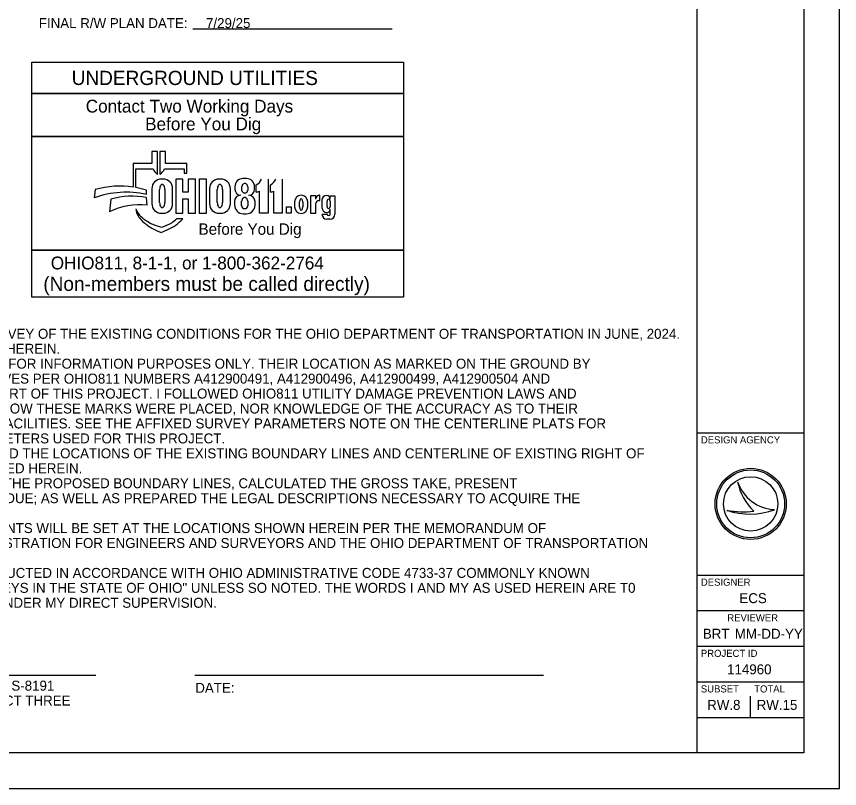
# Model space of a CAD drawing. Extents: x 0 to 34, y 0 to 22.
# Drawn here: x 22.43 to 34, y 0 to 10.85 of the extents above; entities that cross this region are included whole.
import ezdxf

# ---------------------------------------------------------------- set-up
doc = ezdxf.new("R2010")
doc.units = 0
for name, color, linetype in [('Default', 7, 'Continuous'), ('SH_Border', 7, 'Continuous'), ('SH_Cut_Line', 7, 'Continuous'), ('SH_Data', 7, 'Continuous'), ('SH_Text', 7, 'Continuous')]:
    doc.layers.add(name, color=color, linetype=linetype)

msp = doc.modelspace()

# ---------------------------------------------------------------- linework, layer by layer
at = {"layer": 'Default'}
for p, q in [((17.674, 1.594), (23.542, 1.594)), ((24.937, 1.594), (29.837, 1.594))]:
    msp.add_line(p, q, dxfattribs=at)
at = {"layer": 'SH_Border'}
for p, q in [((32, 0.5), (32, 21.5)), ((32, 5), (33.5, 5)), ((32, 3), (33.5, 3)), ((32, 2.5), (33.5, 2.5)), ((32, 2), (33.5, 2)), ((32, 1.5), (33.5, 1.5)), ((32, 1), (33.5, 1))]:
    msp.add_line(p, q, dxfattribs=at)
msp.add_lwpolyline([(1.5, 21.5), (33.5, 21.5), (33.5, 0.5), (1.5, 0.5)], close=True, dxfattribs=at)
at = {"layer": 'SH_Cut_Line'}
msp.add_lwpolyline([(0, 0), (34, 0), (34, 22), (0, 22)], close=True, dxfattribs=at)
at = {"layer": 'SH_Data'}
for p, q in [((24.412, 8.952), (24.332, 8.952)), ((24.332, 8.952), (24.332, 8.785)), ((24.412, 8.635), (24.412, 8.952)), ((24.524, 8.952), (24.444, 8.952)), ((24.444, 8.952), (24.444, 8.635)), ((24.524, 8.785), (24.524, 8.952)), ((24.332, 8.785), (24.069, 8.785)), ((24.069, 8.785), (24.069, 8.451)), ((24.107, 8.444), (24.107, 8.708)), ((24.107, 8.708), (24.348, 8.708)), ((24.508, 8.708), (24.786, 8.708)), ((24.821, 8.785), (24.524, 8.785)), ((24.786, 8.708), (24.786, 8.645)), ((24.821, 8.645), (24.821, 8.785)), ((24.786, 8.645), (24.821, 8.645)), ((25.661, 8.571), (25.612, 8.571)), ((24.489, 8.564), (24.464, 8.564)), ((24.767, 8.563), (24.666, 8.563)), ((24.666, 8.563), (24.666, 8.085)), ((25.3, 8.564), (25.275, 8.564)), ((25.498, 8.457), (25.498, 8.42)), ((25.597, 8.403), (25.597, 8.462)), ((25.678, 8.462), (25.678, 8.403)), ((25.775, 8.42), (25.775, 8.457)), ((25.798, 8.382), (25.798, 8.484)), ((25.965, 8.563), (25.965, 8.085)), ((25.998, 8.382), (25.998, 8.484)), ((26.165, 8.563), (26.165, 8.085)), ((23.534, 8.417), (23.52, 8.3)), ((24.253, 8.349), (24.253, 8.407)), ((24.331, 8.43), (24.331, 8.218)), ((24.44, 8.235), (24.44, 8.418)), ((24.514, 8.418), (24.514, 8.235)), ((24.623, 8.218), (24.623, 8.43)), ((25.142, 8.43), (25.142, 8.218)), ((25.25, 8.235), (25.25, 8.418)), ((25.325, 8.418), (25.325, 8.235)), ((25.434, 8.218), (25.434, 8.43)), ((25.846, 8.085), (25.846, 8.396)), ((26.046, 8.085), (26.046, 8.396)), ((26.694, 8.336), (26.688, 8.336)), ((26.694, 8.261), (26.694, 8.336)), ((23.755, 8.281), (23.733, 8.102)), ((24.263, 8.198), (24.254, 8.304)), ((24.767, 8.085), (24.767, 8.287)), ((25.493, 8.25), (25.493, 8.199)), ((25.593, 8.19), (25.593, 8.252)), ((25.678, 8.252), (25.678, 8.19)), ((25.781, 8.199), (25.781, 8.25)), ((26.339, 8.176), (26.339, 8.243)), ((26.406, 8.174), (26.406, 8.243)), ((26.454, 8.243), (26.454, 8.174)), ((26.521, 8.243), (26.521, 8.176)), ((26.634, 8.328), (26.561, 8.328)), ((26.561, 8.328), (26.561, 8.085)), ((26.634, 8.281), (26.634, 8.328)), ((26.683, 8.261), (26.694, 8.261)), ((26.723, 8.163), (26.723, 8.267)), ((26.795, 8.177), (26.795, 8.253)), ((26.837, 8.283), (26.837, 8.329)), ((26.837, 8.329), (26.903, 8.329)), ((26.837, 8.253), (26.837, 8.177)), ((26.903, 8.329), (26.903, 8.071)), ((24.106, 8.145), (24.111, 8.118)), ((26.634, 8.085), (26.634, 8.212)), ((26.837, 8.071), (26.837, 8.14)), ((24.464, 8.085), (24.489, 8.085)), ((24.666, 8.085), (24.767, 8.085)), ((24.765, 8.005), (24.679, 8.005)), ((24.762, 8.002), (24.765, 8.005)), ((25.275, 8.085), (25.3, 8.085)), ((25.614, 8.078), (25.66, 8.078)), ((25.965, 8.085), (25.846, 8.085)), ((26.165, 8.085), (26.046, 8.085)), ((26.561, 8.085), (26.634, 8.085)), ((26.723, 8.071), (26.795, 8.071)), ((26.833, 8.001), (26.792, 8.001)), ((24.471, 7.884), (24.382, 7.914)), ((24.532, 7.91), (24.471, 7.884)), ((24.406, 7.838), (24.462, 7.814)), ((24.462, 7.814), (24.557, 7.855)), ((27.868, 6.906), (22.643, 6.906)), ((32.567, 4.31), (32.567, 4.31)), ((32.75, 4), (32.75, 4)), ((32.417, 3.91), (32.417, 3.91)), ((33.087, 3.919), (33.087, 3.919)), ((32.75, 1), (32.75, 1.3))]:
    msp.add_line(p, q, dxfattribs=at)
for points in [[(22.643, 10.206), (27.868, 10.206), (27.868, 9.766), (22.643, 9.766)], [(22.643, 9.766), (27.868, 9.766), (27.868, 9.161), (22.643, 9.161)], [(22.643, 9.161), (27.868, 9.161), (27.868, 7.566), (22.643, 7.566)], [(26.223, 8.174), (26.289, 8.174), (26.289, 8.085), (26.223, 8.085)], [(22.643, 7.566), (27.868, 7.566), (27.868, 6.906), (22.643, 6.906)]]:
    msp.add_lwpolyline(points, close=True, dxfattribs=at)
for points in [[(24.767, 8.287), (24.843, 8.287), (24.843, 8.085), (24.945, 8.085), (24.945, 8.563), (24.843, 8.563), (24.843, 8.382), (24.767, 8.382), (24.767, 8.563)], [(24.995, 8.085), (25.098, 8.085), (25.098, 8.563), (24.995, 8.563), (24.995, 8.085)], [(25.579, 8.337), (25.579, 8.337)], [(25.695, 8.337), (25.695, 8.337)]]:
    msp.add_lwpolyline(points, dxfattribs=at)
for radius in [0.5, 0.477, 0.477, 0.382]:
    msp.add_circle((32.75, 4), radius, dxfattribs=at)
for centre, radius, start, end in [((24.484, 8.763), 0.147, 201.9296, 240.7469), ((24.372, 8.763), 0.147, 299.2531, 338.0704), ((25.612, 8.457), 0.114, 90, 180), ((25.661, 8.457), 0.114, 0, 90), ((23.878, 7.242), 1.224, 81.0007, 106.3144), ((24.464, 8.43), 0.134, 90, 180), ((24.489, 8.43), 0.134, 0, 90), ((25.275, 8.43), 0.134, 90, 180), ((25.3, 8.43), 0.134, 0, 90), ((25.747, 8.606), 0.132, 292.5572, 340.7355), ((25.947, 8.606), 0.132, 292.5572, 340.7355), ((23.972, 7.047), 1.332, 77.8238, 109.8274), ((23.878, 7.242), 1.224, 72.1402, 79.2074), ((25.579, 8.25), 0.0865, 90, 180), ((25.582, 8.42), 0.0837, 180, 268.1442), ((25.691, 8.42), 0.0837, 272.2058, 0), ((25.695, 8.25), 0.0865, 0, 90), ((25.786, 8.514), 0.132, 275.1733, 297.0931), ((25.986, 8.514), 0.132, 275.1733, 297.0931), ((26.434, 8.243), 0.0956, 92.5886, 180), ((26.426, 8.243), 0.0956, 0, 87.4114), ((26.688, 8.281), 0.0548, 90, 180), ((26.791, 8.267), 0.0686, 92.6865, 180), ((26.785, 8.283), 0.0524, 0, 86.9262), ((24.054, 7.229), 1.094, 79.44, 105.8467), ((24.464, 8.218), 0.134, 180, 270), ((24.489, 8.218), 0.134, 270, 0), ((25.275, 8.218), 0.134, 180, 270), ((25.3, 8.218), 0.134, 270, 0), ((26.683, 8.212), 0.0493, 90, 180), ((24.161, 7.254), 0.95, 83.8248, 116.8021), ((24.386, 8.252), 0.3, 201.0457, 232.5314), ((24.322, 8.154), 0.214, 189.6817, 216.0884), ((25.614, 8.199), 0.121, 180, 270), ((25.66, 8.199), 0.121, 270, 0), ((26.434, 8.176), 0.0956, 180, 267.4114), ((26.426, 8.176), 0.0956, 272.5886, 0), ((26.792, 8.163), 0.0692, 180, 265.7132), ((26.791, 8.14), 0.0467, 264.7825, 0), ((24.522, 8.3), 0.461, 216.0884, 235.7167), ((24.674, 8.628), 0.773, 232.5314, 241.794), ((24.318, 8.404), 0.538, 293.4582, 312.0712), ((24.318, 8.404), 0.599, 293.4582, 317.8286), ((26.792, 8.071), 0.0699, 180, 270), ((26.833, 8.071), 0.0699, 270, 0), ((24.77, 8.664), 0.903, 235.7167, 246.2325), ((24.547, 8.391), 0.504, 241.794, 250.9821), ((33.116, 4.498), 0.58, 198.9257, 198.9319), ((33.347, 4.47), 0.796, 191.6379, 191.6421), ((33.116, 4.498), 0.58, 198.9319, 267.1657), ((33.347, 4.47), 0.796, 191.6421, 226.0947), ((32.739, 4.87), 1.013, 251.4576, 290.0832), ((32.648, 5.154), 1.266, 259.4964, 259.4995), ((32.739, 4.87), 1.013, 251.4527, 251.4576), ((32.648, 5.154), 1.266, 259.4995, 276.6672)]:
    msp.add_arc(centre, radius, start, end, dxfattribs=at)
for centre, major_axis, ratio, start_param, end_param in [((24.477, 8.418), (0, 0.0723), 0.514403, 4.712389, 7.853982), ((25.288, 8.418), (0, 0.0723), 0.514403, 4.712389, 7.853982), ((25.637, 8.462), (0.0404, 0), 0.969373, 0, 3.141593), ((25.637, 8.403), (0.0404, 0), 0.818453, 3.141593, 6.283185), ((24.477, 8.235), (0, 0.0723), 0.514403, 1.570796, 4.712389), ((25.288, 8.235), (0, 0.0723), 0.514403, 1.570796, 4.712389), ((25.636, 8.252), (0, 0.0535), 0.794529, 4.712389, 7.853982), ((26.43, 8.243), (0, 0.0434), 0.553236, 4.712389, 7.853982), ((26.816, 8.253), (0, 0.0275), 0.777179, 4.712389, 7.853982), ((25.636, 8.19), (0.0425, 0), 0.959837, 3.141593, 6.283185), ((26.43, 8.174), (0, 0.046), 0.522014, 1.570796, 4.712389), ((26.816, 8.177), (0, 0.0275), 0.777179, 1.570796, 4.712389), ((26.816, 8.071), (0.0214, 0), 0.959012, 3.141593, 6.283185)]:
    msp.add_ellipse(centre, major_axis=major_axis, ratio=ratio, start_param=start_param, end_param=end_param, dxfattribs=at)
at = {"layer": 'SH_Text'}
msp.add_line((24.907, 10.677), (27.71, 10.677), dxfattribs=at)

# ---------------------------------------------------------------- texts
at = {"layer": 'Default'}
for s, p in [('I, BRETT R. TIEBEN, P.S. HAVE CONDUCTED A SURVEY OF THE EXISTING CONDITIONS FOR THE OHIO DEPARTMENT OF TRANSPORTATION IN JUNE, 2024.', (17.673, 6.32)), ('THE RESULTS OF THAT SURVEY ARE CONTAINED HEREIN.', (17.673, 6.11)), ('UNDERGROUND UTILITY LOCATIONS ARE SHOWN FOR INFORMATION PURPOSES ONLY. THEIR LOCATION AS MARKED ON THE GROUND BY', (17.673, 5.9)), ('THE UTILITY COMPANY OR THEIR REPRESENTATIVES PER OHIO811 NUMBERS A412900491, A412900496, A412900499, A412900504 AND', (17.673, 5.69)), ('A412900516 WERE SURVEYED AND MAPPED AS PART OF THIS PROJECT. I FOLLOWED OHIO811 UTILITY DAMAGE PREVENTION LAWS AND', (17.673, 5.48)), ('HAVE NO DIRECT KNOWLEDGE OR CONTROL OF HOW THESE MARKS WERE PLACED, NOR KNOWLEDGE OF THE ACCURACY AS TO THEIR', (17.673, 5.27)), ('INTENDED DEPICTION OF SUBSURFACE UTILITY FACILITIES. SEE THE AFFIXED SURVEY PARAMETERS NOTE ON THE CENTERLINE PLATS FOR', (17.673, 5.06)), ('THE HORIZONTAL AND VERTICAL SURVEY PARAMETERS USED FOR THIS PROJECT.', (17.673, 4.85)), ('AS PART OF THIS PROJECT I HAVE REESTABLISHED THE LOCATIONS OF THE EXISTING BOUNDARY LINES AND CENTERLINE OF EXISTING RIGHT OF', (17.673, 4.64)), ('WAY OF S.R. 603 FOR PROPERTY TAKES CONTAINED HEREIN.', (17.673, 4.43)), ('AS PART OF THIS PROJECT I HAVE ESTABLISHED THE PROPOSED BOUNDARY LINES, CALCULATED THE GROSS TAKE, PRESENT', (17.673, 4.22)), ('ROAD OCCUPIED (PRO), NET TAKE, AND NET RESIDUE; AS WELL AS PREPARED THE LEGAL DESCRIPTIONS NECESSARY TO ACQUIRE THE', (17.673, 4.01)), ('AS PART OF THIS WORK, RIGHT OF WAY MONUMENTS WILL BE SET AT THE LOCATIONS SHOWN HEREIN PER THE MEMORANDUM OF', (17.673, 3.59)), ('UNDERSTANDING BETWEEN THE BOARD OF REGISTRATION FOR ENGINEERS AND SURVEYORS AND THE OHIO DEPARTMENT OF TRANSPORTATION', (17.673, 3.38)), ('ALL OF MY WORK CONTAINED HEREIN WAS CONDUCTED IN ACCORDANCE WITH OHIO ADMINISTRATIVE CODE 4733-37 COMMONLY KNOWN', (17.673, 2.96)), ('AS "MINIMUM STANDARDS FOR BOUNDARY SURVEYS IN THE STATE OF OHIO" UNLESS SO NOTED. THE WORDS I AND MY AS USED HEREIN ARE T0', (17.673, 2.75)), ('MEAN EITHER MYSELF OR SOMEONE WORKING UNDER MY DIRECT SUPERVISION. ', (17.673, 2.54)), ('BRETT R. TIEBEN, PROFESSIONAL SURVEYOR NO. S-8191', (17.674, 1.376)), ('DATE:', (24.941, 1.345)), ('OHIO DEPARTMENT OF TRANSPORTATION DISTRICT THREE', (17.674, 1.166))]:
    msp.add_text(s, height=0.14, dxfattribs=at).set_placement(p)
at = {"layer": 'SH_Data'}
for s, height, p in [('UNDERGROUND UTILITIES', 0.2, (23.203, 9.886)), ('Contact Two Working Days', 0.18, (23.401, 9.499)), ('Before You Dig', 0.18, (24.236, 9.249)), ('Before You Dig', 0.15972, (24.987, 7.782)), ('OHIO811, 8-1-1, or 1-800-362-2764', 0.18, (22.909, 7.295)), ('(Non-members must be called directly)', 0.2, (22.804, 6.993)), ('DESIGN AGENCY', 0.1, (32.05, 4.85)), ('DESIGNER', 0.1, (32.05, 2.85)), ('ECS', 0.14, (32.592, 2.605)), ('REVIEWER', 0.1, (32.422, 2.35)), ('BRT', 0.14, (32.078, 2.105)), ('MM-DD-YY', 0.14, (32.527, 2.105)), ('PROJECT ID', 0.1, (32.05, 1.85)), ('114960', 0.14, (32.419, 1.605)), ('SUBSET', 0.1, (32.05, 1.35)), ('TOTAL', 0.1, (32.8, 1.35)), ('RW.8', 0.14, (32.139, 1.105)), ('RW.15', 0.14, (32.835, 1.105))]:
    msp.add_text(s, height=height, dxfattribs=at).set_placement(p)
at = {"layer": 'SH_Text'}
msp.add_text('FINAL R/W PLAN DATE:     7/29/25', height=0.14, dxfattribs=at).set_placement((22.741, 10.686))

doc.saveas('drawing.dxf')
